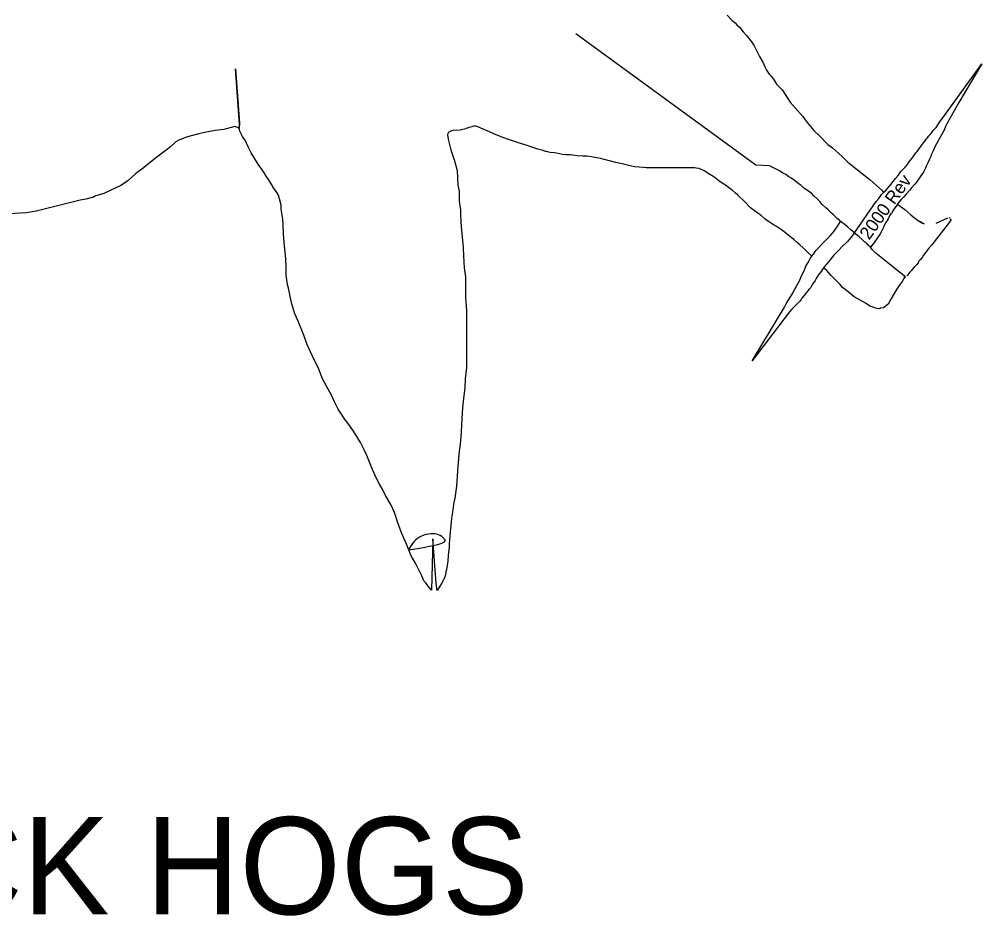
# Model space of a CAD drawing. Extents: x 1334737.7 to 1334827.2, y 402732.3 to 402753.5.
# Drawn here: x 1334811.6711 to 1334811.68251, y 402753.22596 to 402753.23659 of the extents above; entities that cross this region are included whole.
import ezdxf

# ---------------------------------------------------------------- set-up
doc = ezdxf.new("R2010")
doc.units = 0
doc.layers.add('R_Draft', color=7, linetype='Continuous')

msp = doc.modelspace()

# ---------------------------------------------------------------- linework, layer by layer
at = {"layer": 'R_Draft'}
for points in [[(1334811.6794972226, 402753.23663394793), (1334811.6795515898, 402753.2365752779), (1334811.6795887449, 402753.2365420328), (1334811.679610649, 402753.2365197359), (1334811.679640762, 402753.23649079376), (1334811.6796861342, 402753.23643799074), (1334811.679729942, 402753.23638831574), (1334811.6797831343, 402753.23631947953), (1334811.679814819, 402753.2362717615), (1334811.6798488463, 402753.23620761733), (1334811.6798797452, 402753.2361465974), (1334811.6799169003, 402753.23607932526), (1334811.6799325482, 402753.2360413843), (1334811.6799470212, 402753.23601244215), (1334811.6799610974, 402753.23598154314), (1334811.6799935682, 402753.23593656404), (1334811.6800150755, 402753.2359119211), (1334811.6800451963, 402753.2358747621), (1334811.6800819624, 402753.235814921), (1334811.6801457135, 402753.2357484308), (1334811.6802419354, 402753.2356013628), (1334811.6802998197, 402753.2355364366), (1334811.6803909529, 402753.2354339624), (1334811.68044532, 402753.23536394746), (1334811.68052433, 402753.2352653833), (1334811.6805927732, 402753.2351988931), (1334811.680690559, 402753.2351007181), (1334811.6807437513, 402753.23506355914), (1334811.6808579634, 402753.23495952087), (1334811.6809244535, 402753.23489341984), (1334811.6810191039, 402753.23481714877), (1334811.681096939, 402753.2347580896), (1334811.681189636, 402753.23468338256), (1334811.681262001, 402753.23461962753), (1334811.6813382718, 402753.2345531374), (1334811.681357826, 402753.2345378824)], [(1334811.6815927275, 402753.23354410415), (1334811.681262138, 402753.23381026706), (1334811.6812158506, 402753.23385571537), (1334811.6811950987, 402753.2338818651), (1334811.6811668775, 402753.2339082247), (1334811.6811490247, 402753.23392544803), (1334811.6811268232, 402753.233943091), (1334811.6810967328, 402753.23397338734), (1334811.6810589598, 402753.2340080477), (1334811.6810224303, 402753.2340375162), (1334811.6809908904, 402753.23406491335), (1334811.680962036, 402753.2340900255), (1334811.6809244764, 402753.23411949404), (1334811.6808954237, 402753.234147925), (1334811.680852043, 402753.23417864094), (1334811.680800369, 402753.2342222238), (1334811.6807607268, 402753.2342612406), (1334811.6807484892, 402753.23427327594), (1334811.6807300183, 402753.2342913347), (1334811.6806905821, 402753.234329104), (1334811.6806642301, 402753.23435006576), (1334811.6806229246, 402753.2343880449), (1334811.6805928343, 402753.23442581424), (1334811.680563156, 402753.2344552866), (1334811.6805243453, 402753.2344928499), (1334811.6804963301, 402753.23452315), (1334811.6804512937, 402753.23455324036), (1334811.680401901, 402753.2345883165), (1334811.680371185, 402753.2346142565), (1334811.680350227, 402753.23463003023), (1334811.6803234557, 402753.2346503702), (1334811.680291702, 402753.2346748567), (1334811.6802742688, 402753.2346881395), (1334811.6802551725, 402753.2347024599), (1334811.6802265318, 402753.23471678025), (1334811.6801908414, 402753.2347439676), (1334811.6801563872, 402753.2347628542), (1334811.6801138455, 402753.2347883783), (1334811.6800451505, 402753.234824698), (1334811.6799986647, 402753.2348500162), (1334811.6798359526, 402753.23485665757), (1334811.6777006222, 402753.2364150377)], [(1334811.6810038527, 402753.2340544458), (1334811.681262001, 402753.23442602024), (1334811.681293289, 402753.23446239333), (1334811.6813265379, 402753.23450698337), (1334811.681371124, 402753.2345531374), (1334811.681436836, 402753.2346286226), (1334811.681461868, 402753.2346610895), (1334811.6814919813, 402753.2346994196), (1334811.6815213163, 402753.2347342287), (1334811.68155574, 402753.23478194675), (1334811.6816069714, 402753.2348312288), (1334811.6816339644, 402753.2348640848), (1334811.6816511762, 402753.23489576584), (1334811.6816711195, 402753.23492079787), (1334811.6817078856, 402753.234966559), (1334811.6817309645, 402753.23500371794), (1334811.6817493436, 402753.23501975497), (1334811.6817794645, 402753.2350627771), (1334811.6817896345, 402753.23507725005), (1334811.6818080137, 402753.23510267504), (1334811.6818252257, 402753.23512653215), (1334811.6818557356, 402753.2351625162), (1334811.6818694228, 402753.23517855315), (1334811.6818838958, 402753.2351988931), (1334811.6819077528, 402753.23522783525), (1334811.68192144, 402753.2352430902), (1334811.6819382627, 402753.2352653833), (1334811.681972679, 402753.2353029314), (1334811.6819922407, 402753.2353338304), (1334811.68201844, 402753.2353764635), (1334811.6820411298, 402753.23540267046), (1334811.6825132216, 402753.2360566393), (1334811.6822429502, 402753.23560097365), (1334811.6821005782, 402753.2353471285), (1334811.682084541, 402753.2353158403), (1334811.682067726, 402753.2352712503), (1334811.6820348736, 402753.2352161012), (1334811.6820192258, 402753.23518715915), (1334811.6820047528, 402753.2351597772), (1334811.6819922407, 402753.23513670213), (1334811.681960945, 402753.2350823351), (1334811.6819492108, 402753.23505417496), (1334811.6819382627, 402753.235027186), (1334811.6819194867, 402753.234988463), (1334811.6819077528, 402753.23495952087), (1334811.681892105, 402753.23492822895), (1334811.6818780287, 402753.23489341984), (1334811.6818561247, 402753.23484609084), (1334811.6818455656, 402753.2348187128), (1334811.6818252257, 402753.23478116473), (1334811.6818107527, 402753.2347580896), (1334811.6817638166, 402753.2346884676), (1334811.6817399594, 402753.2346544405), (1334811.6817211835, 402753.2346325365), (1334811.6816820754, 402753.23458560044), (1334811.6816554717, 402753.2345550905), (1334811.6816179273, 402753.23451245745), (1334811.6815885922, 402753.2344811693), (1334811.6815584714, 402753.23444987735), (1334811.6815357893, 402753.2344228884), (1334811.6815193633, 402753.23440098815), (1334811.6814990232, 402753.2343712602), (1334811.6814833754, 402753.23434935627), (1334811.6814595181, 402753.23431494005), (1334811.6814466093, 402753.23428873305), (1334811.681436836, 402753.23427817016), (1334811.6814215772, 402753.23425431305), (1334811.681404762, 402753.2342214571), (1334811.6813918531, 402753.234200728), (1334811.681376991, 402753.2341768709), (1334811.6813570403, 402753.23414010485), (1334811.681342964, 402753.2341095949), (1334811.681332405, 402753.2340849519), (1334811.6813073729, 402753.23404114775), (1334811.681296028, 402753.23402354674), (1334811.6812827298, 402753.23400047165), (1334811.68124987, 402753.23395392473), (1334811.6812314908, 402753.2339288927), (1334811.6811958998, 402753.23388195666)], [(1334811.6742658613, 402753.2336429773), (1334811.6742619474, 402753.2337489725), (1334811.6742525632, 402753.23385809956), (1334811.6742451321, 402753.2339429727), (1334811.674237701, 402753.23404114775), (1334811.6742314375, 402753.23414988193), (1334811.6742267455, 402753.234217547), (1334811.6742099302, 402753.2343352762), (1334811.6742064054, 402753.2343810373), (1334811.6741899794, 402753.23445770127), (1334811.6741755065, 402753.2344999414), (1334811.6741559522, 402753.2345316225), (1334811.6741414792, 402753.2345562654), (1334811.6741270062, 402753.2345773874), (1334811.674086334, 402753.2346442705), (1334811.674055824, 402753.2346958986), (1334811.674030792, 402753.2347256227), (1334811.674002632, 402753.2347741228), (1334811.673937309, 402753.23486877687), (1334811.6738532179, 402753.2350005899), (1334811.673819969, 402753.23506473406), (1334811.6737855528, 402753.23514295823), (1334811.6737491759, 402753.23519615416), (1334811.6737194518, 402753.23525990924), (1334811.6737143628, 402753.23527751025), (1334811.6737100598, 402753.2352911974), (1334811.6737108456, 402753.2353068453), (1334811.6737131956, 402753.2353322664), (1334811.6737143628, 402753.2353432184), (1334811.6736682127, 402753.23599875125), (1334811.6737155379, 402753.2353545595), (1334811.6737096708, 402753.23529511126), (1334811.6736596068, 402753.2353131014), (1334811.6735301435, 402753.23527711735), (1334811.6734272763, 402753.2352653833), (1334811.673298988, 402753.2352430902), (1334811.6732305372, 402753.23522783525), (1334811.673124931, 402753.2351988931), (1334811.6730842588, 402753.23518833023), (1334811.672995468, 402753.23515391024), (1334811.6729606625, 402753.23513083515), (1334811.6728953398, 402753.23507334), (1334811.6728464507, 402753.23503539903), (1334811.6727963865, 402753.23499706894), (1334811.6727326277, 402753.23494974), (1334811.6726598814, 402753.23489341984), (1334811.6725738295, 402753.2348214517), (1334811.6724862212, 402753.2347580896), (1334811.6723946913, 402753.23467555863), (1334811.672315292, 402753.23461962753), (1334811.6723039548, 402753.23461415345)], [(1334811.680498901, 402753.23377635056), (1334811.680496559, 402753.23377987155), (1334811.6804390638, 402753.2338338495), (1334811.680396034, 402753.2338741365), (1334811.6803557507, 402753.23391207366), (1334811.6803334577, 402753.23393280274), (1334811.6802873, 402753.2339734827), (1334811.6802544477, 402753.23399655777), (1334811.6802184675, 402753.2340266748), (1334811.6801875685, 402753.23405170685), (1334811.6801374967, 402753.2340884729), (1334811.6800784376, 402753.23412993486), (1334811.6800451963, 402753.234147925), (1334811.6799857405, 402753.23418703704), (1334811.6799470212, 402753.2342163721), (1334811.679902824, 402753.234257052), (1334811.6798601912, 402753.23428599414), (1334811.67981443, 402753.2343188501), (1334811.679772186, 402753.2343513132), (1334811.6797049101, 402753.2344205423), (1334811.6796204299, 402753.23450189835), (1334811.679590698, 402753.23452732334), (1334811.679553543, 402753.2345605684), (1334811.679512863, 402753.2345895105), (1334811.6794745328, 402753.23461962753), (1334811.679454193, 402753.2346325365), (1334811.6794342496, 402753.2346442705), (1334811.6793982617, 402753.2346720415), (1334811.6793767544, 402753.23468651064), (1334811.6793388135, 402753.2347170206), (1334811.6792715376, 402753.2347580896), (1334811.6792308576, 402753.2347866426), (1334811.6791616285, 402753.23481714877), (1334811.6791287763, 402753.2348214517), (1334811.6791064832, 402753.2348245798), (1334811.6790767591, 402753.2348245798), (1334811.6790392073, 402753.2348245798), (1334811.6790098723, 402753.2348245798), (1334811.678942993, 402753.2348245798), (1334811.6789128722, 402753.2348245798), (1334811.678835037, 402753.2348245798), (1334811.6787974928, 402753.2348245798), (1334811.678736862, 402753.2348245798), (1334811.678699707, 402753.2348245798), (1334811.6786328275, 402753.2348245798), (1334811.6786019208, 402753.2348245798), (1334811.6785573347, 402753.2348245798), (1334811.6785354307, 402753.2348245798), (1334811.6785021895, 402753.23482692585), (1334811.6783997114, 402753.2348367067), (1334811.6783594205, 402753.2348433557), (1334811.6782663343, 402753.2348664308), (1334811.6781752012, 402753.23488598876), (1334811.67807077, 402753.2349168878), (1334811.677994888, 402753.23493448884), (1334811.677887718, 402753.234953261), (1334811.677837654, 402753.23496304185), (1334811.6777848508, 402753.23496343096), (1334811.6777152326, 402753.2349677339), (1334811.6776358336, 402753.2349771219), (1334811.6775795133, 402753.234978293), (1334811.6775427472, 402753.23498377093), (1334811.6774731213, 402753.235000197), (1334811.6774445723, 402753.235001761), (1334811.6773972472, 402753.2350072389), (1334811.6773815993, 402753.23500880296), (1334811.6773553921, 402753.2350166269), (1334811.6773424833, 402753.2350166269), (1334811.6773158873, 402753.23502914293), (1334811.677250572, 402753.23504752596), (1334811.677179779, 402753.235068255), (1334811.6771254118, 402753.2350885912), (1334811.677086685, 402753.2351007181), (1334811.6769846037, 402753.2351347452), (1334811.6768911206, 402753.23516486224), (1334811.6767976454, 402753.23520006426), (1334811.6767299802, 402753.2352262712), (1334811.6766787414, 402753.2352501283), (1334811.6766212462, 402753.23527594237), (1334811.6765750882, 402753.23529628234), (1334811.6765336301, 402753.23531271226), (1334811.6765129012, 402753.23531936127), (1334811.676486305, 402753.2353174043), (1334811.676467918, 402753.23531114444), (1334811.676451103, 402753.23530762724), (1334811.6764346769, 402753.2353021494), (1334811.676426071, 402753.2352978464), (1334811.676402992, 402753.2352892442), (1334811.676381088, 402753.2352810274), (1334811.6763615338, 402753.2352778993), (1334811.676331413, 402753.2352716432), (1334811.6762465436, 402753.2352689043), (1334811.676218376, 402753.23525755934), (1334811.6762082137, 402753.23525130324), (1334811.6761953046, 402753.2352470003), (1334811.6761863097, 402753.23523995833), (1334811.6761820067, 402753.23523213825), (1334811.6761800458, 402753.23521727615), (1334811.6761863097, 402753.2351629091), (1334811.676219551, 402753.23503618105), (1334811.6762614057, 402753.2349090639)], [(1334811.6762614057, 402753.2349090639), (1334811.6762938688, 402753.2347917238), (1334811.6762985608, 402753.2347056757), (1334811.676303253, 402753.23461962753), (1334811.6763173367, 402753.2345488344), (1334811.6763200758, 402753.23450189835), (1334811.6763200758, 402753.23443462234), (1334811.67632711, 402753.23436852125), (1334811.6763329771, 402753.2343294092), (1334811.6763329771, 402753.234291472), (1334811.6763329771, 402753.234261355), (1334811.676342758, 402753.2341236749), (1334811.676355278, 402753.23400672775), (1334811.676364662, 402753.2338784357), (1334811.676370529, 402753.23377987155), (1334811.676379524, 402753.23364023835), (1334811.676393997, 402753.2335303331), (1334811.6763947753, 402753.233369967), (1334811.676393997, 402753.2332901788), (1334811.6764033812, 402753.23313372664), (1334811.6764033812, 402753.23303711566), (1334811.6764033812, 402753.23290178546), (1334811.6764033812, 402753.2327633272), (1334811.6764033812, 402753.232658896), (1334811.6764033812, 402753.23252473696), (1334811.6764033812, 402753.2324586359), (1334811.676389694, 402753.2323229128), (1334811.6763873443, 402753.2322192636), (1334811.676370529, 402753.2320886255), (1334811.6763595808, 402753.2319806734), (1334811.6763478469, 402753.23178080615), (1334811.676342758, 402753.23168459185), (1334811.676331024, 402753.2315492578), (1334811.676318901, 402753.2314639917), (1334811.676303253, 402753.23128563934), (1334811.676292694, 402753.23116751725), (1334811.676288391, 402753.23104939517), (1334811.676266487, 402753.2309074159), (1334811.676252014, 402753.2308346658), (1334811.676237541, 402753.2307431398), (1334811.676226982, 402753.2306688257), (1334811.6762207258, 402753.2305804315), (1334811.6762113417, 402753.23050728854), (1334811.6761980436, 402753.2303598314), (1334811.6761980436, 402753.2303218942), (1334811.6761894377, 402753.2302295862), (1334811.676183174, 402753.230156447), (1334811.6761706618, 402753.230087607), (1334811.6761663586, 402753.230055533), (1334811.6761604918, 402753.23003441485), (1334811.6761597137, 402753.2300215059), (1334811.6761514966, 402753.2299859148), (1334811.6761421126, 402753.22995657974), (1334811.6761315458, 402753.2299378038), (1334811.6761104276, 402753.2298971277), (1334811.6760568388, 402753.22981303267), (1334811.6760474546, 402753.22989478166), (1334811.6760075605, 402753.2304251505), (1334811.6759915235, 402753.22981772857), (1334811.6759610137, 402753.2298474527), (1334811.6759375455, 402753.2298810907), (1334811.6759238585, 402753.2299018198), (1334811.6758996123, 402753.2299260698), (1334811.6758706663, 402753.2299937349), (1334811.6758033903, 402753.230128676), (1334811.675749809, 402753.23022254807), (1334811.675693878, 402753.2303598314), (1334811.6756395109, 402753.23048655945), (1334811.6755964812, 402753.23060194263), (1334811.675551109, 402753.2307364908), (1334811.6755065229, 402753.2308311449), (1334811.6754435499, 402753.2309394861), (1334811.6754177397, 402753.230998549), (1334811.6753727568, 402753.23107208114), (1334811.6753344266, 402753.2311475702), (1334811.6752906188, 402753.2312484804), (1334811.6752628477, 402753.23131379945), (1334811.6752241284, 402753.23141158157), (1334811.6751928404, 402753.2314800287), (1334811.6751470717, 402753.23156803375), (1334811.6751032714, 402753.23163843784), (1334811.6750563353, 402753.23171431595), (1334811.6750101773, 402753.23178198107), (1334811.6749581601, 402753.2318492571), (1334811.674913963, 402753.2319157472), (1334811.6748838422, 402753.23196307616), (1334811.674838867, 402753.2320491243), (1334811.67480014, 402753.23213595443), (1334811.674750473, 402753.23222786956), (1334811.6746992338, 402753.2323209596), (1334811.6746456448, 402753.2324586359), (1334811.6746010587, 402753.23254898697), (1334811.674513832, 402753.23273829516), (1334811.6744774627, 402753.2328388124), (1334811.6744101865, 402753.2330066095), (1334811.6743706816, 402753.23309304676), (1334811.6743319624, 402753.2332248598), (1334811.6742979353, 402753.23337974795), (1334811.6742842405, 402753.233440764), (1334811.6742693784, 402753.23354988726), (1334811.6742658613, 402753.2336429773)], [(1334811.672315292, 402753.23461962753), (1334811.67210643, 402753.2345206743), (1334811.6720008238, 402753.2344870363), (1334811.6719836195, 402753.2344764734), (1334811.6718913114, 402753.2344526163), (1334811.6718244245, 402753.23444010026), (1334811.6715404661, 402753.2343681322), (1334811.671444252, 402753.2343470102), (1334811.671305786, 402753.23430985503), (1334811.6711884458, 402753.2342906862), (1334811.6711137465, 402753.23428834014), (1334811.6709236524, 402753.23427621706)], [(1334811.6815147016, 402753.23439427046), (1334811.681518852, 402753.2343911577), (1334811.6816006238, 402753.234329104), (1334811.6816722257, 402753.2342676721), (1334811.681735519, 402753.23421641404), (1334811.6817473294, 402753.23420571)], [(1334811.6819717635, 402753.2341701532), (1334811.682111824, 402753.23423307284)], [(1334811.6821325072, 402753.23423094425), (1334811.6821386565, 402753.2342264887)], [(1334811.6810030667, 402753.2340544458), (1334811.6809631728, 402753.23399890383), (1334811.6809213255, 402753.2339523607), (1334811.6808544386, 402753.2338866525), (1334811.6808219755, 402753.23385379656), (1334811.6807910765, 402753.23381859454), (1334811.6807593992, 402753.2337884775), (1334811.6807288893, 402753.23374819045), (1334811.6806780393, 402753.2336875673), (1334811.6806510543, 402753.23365471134), (1334811.680622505, 402753.23361638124), (1334811.680609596, 402753.23359565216), (1334811.6805747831, 402753.23354988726), (1334811.680552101, 402753.2335131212), (1334811.6805388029, 402753.23348652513), (1334811.680507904, 402753.2334438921), (1334811.680498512, 402753.233429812), (1334811.6804813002, 402753.23340282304), (1334811.680462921, 402753.233380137), (1334811.6804328, 402753.23334337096), (1334811.680419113, 402753.233327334), (1334811.6804050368, 402753.2333066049), (1334811.6803811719, 402753.23327766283), (1334811.680372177, 402753.23326436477), (1334811.6803510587, 402753.23324011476), (1334811.6803181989, 402753.23320451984), (1334811.6802943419, 402753.2331814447), (1334811.6802622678, 402753.2331466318), (1334811.6802356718, 402753.23311729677), (1334811.6797917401, 402753.232536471), (1334811.6800330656, 402753.2329330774), (1334811.6801738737, 402753.23317205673), (1334811.6801965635, 402753.2332099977), (1334811.6802188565, 402753.23324949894), (1334811.6802450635, 402753.23329604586), (1334811.6802732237, 402753.2333386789), (1334811.6802849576, 402753.233366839), (1334811.6803021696, 402753.233393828), (1334811.6803228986, 402753.23343059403), (1334811.6803350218, 402753.233458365), (1334811.6803514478, 402753.23348613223), (1334811.6803702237, 402753.2335244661), (1334811.6803811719, 402753.23354988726), (1334811.680396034, 402753.2335803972), (1334811.680410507, 402753.23361638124), (1334811.6804331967, 402753.2336660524), (1334811.6804464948, 402753.23369186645), (1334811.6804664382, 402753.2337274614), (1334811.680478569, 402753.2337501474), (1334811.680524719, 402753.2338127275), (1334811.680552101, 402753.2338498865), (1334811.6805779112, 402753.23387570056), (1334811.6806185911, 402753.2339210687), (1334811.6806510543, 402753.2339523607), (1334811.680685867, 402753.2339863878), (1334811.680716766, 402753.2340180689), (1334811.6807437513, 402753.2340477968), (1334811.6807621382, 402753.2340716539), (1334811.6807766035, 402753.2340923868), (1334811.6807996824, 402753.23412484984), (1334811.6808407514, 402753.2341886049)], [(1334811.6821428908, 402753.2341969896), (1334811.6819214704, 402753.23391071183), (1334811.6818897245, 402753.23387501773), (1334811.6818708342, 402753.23385364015), (1334811.6818392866, 402753.23381026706), (1334811.6818245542, 402753.2337897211), (1334811.6818060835, 402753.23376066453), (1334811.6817834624, 402753.2337330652), (1334811.68176416, 402753.2337125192), (1334811.6817579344, 402753.23369882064), (1334811.6817425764, 402753.2336799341), (1334811.6817369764, 402753.2336708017), (1334811.681712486, 402753.23364548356), (1334811.6816902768, 402753.23361788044), (1334811.6816786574, 402753.23360667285), (1334811.681658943, 402753.23358550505), (1334811.6816396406, 402753.23356371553), (1334811.681631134, 402753.2335529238), (1334811.681624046, 402753.2335446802)], [(1334811.6815955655, 402753.2335145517), (1334811.6815871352, 402753.23350456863), (1334811.6815717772, 402753.2334775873), (1334811.6815375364, 402753.233432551), (1334811.6815238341, 402753.23341138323), (1334811.6815118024, 402753.23339374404), (1334811.681474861, 402753.233335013), (1334811.6814370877, 402753.2332671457), (1334811.6814036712, 402753.23320862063), (1334811.6813488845, 402753.23316400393), (1334811.681313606, 402753.2331608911), (1334811.6813003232, 402753.2331532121), (1334811.6812523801, 402753.23316151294), (1334811.681224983, 402753.2331727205), (1334811.6811859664, 402753.23318537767), (1334811.6811436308, 402753.2332138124), (1334811.6810809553, 402753.2332513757), (1334811.6810008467, 402753.23329620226), (1334811.6809547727, 402753.233335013), (1334811.680910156, 402753.2333692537), (1334811.68086367, 402753.23340474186), (1334811.6808356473, 402753.2334396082), (1334811.6807607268, 402753.2335174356), (1334811.6807300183, 402753.2335479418), (1334811.6806758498, 402753.23360729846), (1334811.6806488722, 402753.2336311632), (1334811.6806413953, 402753.2336396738)]]:
    msp.add_lwpolyline(points, dxfattribs=at)
for centre, radius, start, end in [((1334811.6818867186, 402753.2343594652), 0.0002075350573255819, 227.80475532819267, 294.1910830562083), ((1334811.6821203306, 402753.2342141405), 2.0753505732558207e-05, 54.057888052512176, 114.19108273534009), ((1334811.6821264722, 402753.2342096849), 2.075350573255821e-05, 322.28009745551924, 54.05788756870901), ((1334811.6815797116, 402753.2335279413), 2.0753505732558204e-05, 319.82076600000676, 51.16211336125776), ((1334811.6816083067, 402753.23355820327), 2.0753505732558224e-05, 231.16211359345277, 319.3323140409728)]:
    msp.add_arc(centre, radius, start, end, dxfattribs=at)
msp.add_spline([(1334811.6757216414, 402753.2302960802), (1334811.6757826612, 402753.23039034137), (1334811.6759840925, 402753.2304853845), (1334811.6760752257, 402753.23047404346), (1334811.6761456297, 402753.2304224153), (1334811.676196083, 402753.2303320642)], degree=3, dxfattribs=at)

# ---------------------------------------------------------------- texts
msp.add_text('2000 Rev', height=0.00015350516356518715, rotation=54.479691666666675, dxfattribs=at).set_placement((1334811.681177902, 402753.2339597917))
msp.add_text('RAZORBACK HOGS', height=0.0011531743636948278, dxfattribs=at).set_placement((1334811.6625769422, 402753.225971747))

doc.saveas('drawing.dxf')
